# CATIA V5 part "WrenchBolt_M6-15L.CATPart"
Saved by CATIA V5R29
Part number: WrenchBolt_M6-15L
Source: Unknown
Bounding box of the stored display mesh (mm): x -5.11 to 5.11, y -5.11 to 5.11, z -15 to 6
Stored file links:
  C:\가치같이\SmartFactory_BoxErectorConveyor\Boxing(under)\WrenchBolt_M6-15L.CATPart
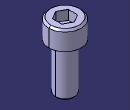
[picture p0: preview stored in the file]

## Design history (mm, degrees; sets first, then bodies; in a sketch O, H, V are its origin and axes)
Body1 (main body)
  Solid1 "PartBody": solid without history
